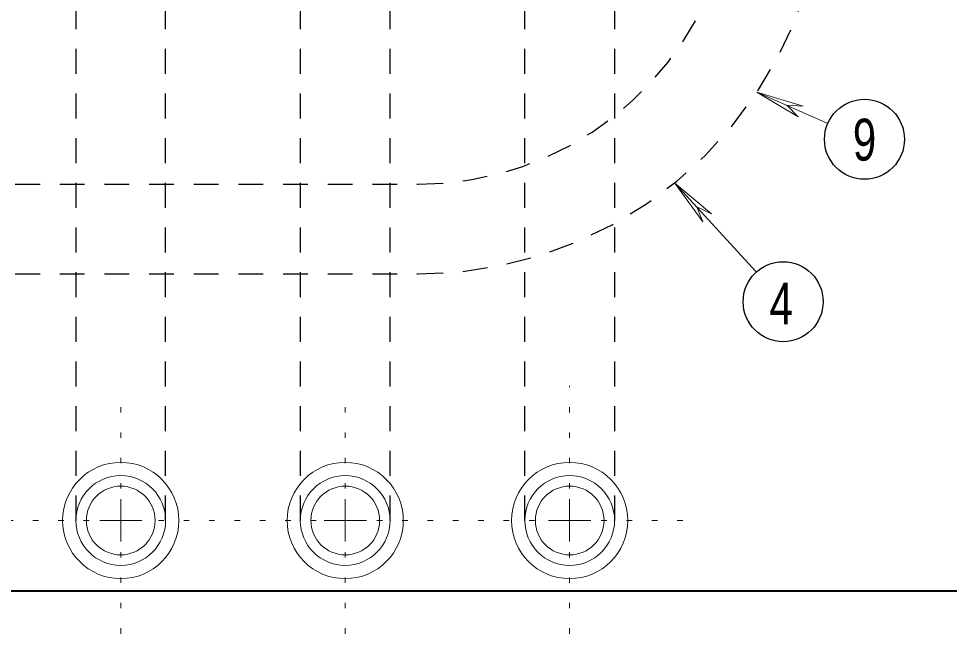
# Model space of a CAD drawing. Extents: x 312583 to 312854, y 144419 to 144597.
# Drawn here: x 312756.71 to 312773.6, y 144437.08 to 144448.42 of the extents above; entities that cross this region are included whole.
import ezdxf

# ---------------------------------------------------------------- set-up
doc = ezdxf.new("R2010")
doc.units = 0
doc.header["$LTSCALE"] = 0.3
doc.linetypes.add('DOTTED', pattern=[1.5, 0.3, -1.2])
doc.linetypes.add('SHORT_DASHED', pattern=[2.7, 1.5, -1.2])
doc.layers.add('1', color=7, linetype='Continuous', lineweight=25)
doc.layers.add('2', color=7, linetype='Continuous', lineweight=13)

msp = doc.modelspace()

# ---------------------------------------------------------------- linework, layer by layer
at = {"layer": '1', "linetype": 'SHORT_DASHED'}
for p, q in [((312757.7576, 144439.315), (312757.7576, 144450.654)), ((312759.383, 144439.315), (312759.383, 144449.182)), ((312761.8286, 144439.315), (312761.8286, 144449.1974)), ((312763.454, 144439.315), (312763.454, 144449.113)), ((312767.5326, 144439.315), (312767.5326, 144448.9827)), ((312765.8996, 144439.315), (312765.8996, 144448.9444)), ((312754.2233, 144445.41), (312763.9676, 144445.41)), ((312754.2233, 144443.7847), (312763.9676, 144443.7847))]:
    msp.add_line(p, q, dxfattribs=at)
at = {"layer": '1', "lineweight": 40}
msp.add_line((312733.8913, 144438.0347), (312778.611, 144438.0347), dxfattribs=at)
at = {"layer": '1', "lineweight": 13}
for centre, radius in [((312758.5684, 144439.3125), 1.0542), ((312762.6413, 144439.3125), 1.0542), ((312766.7142, 144439.3125), 1.0542), ((312758.5684, 144439.3125), 0.8146), ((312762.6413, 144439.3125), 0.8146), ((312766.7142, 144439.3125), 0.8146), ((312758.5684, 144439.3125), 0.6232), ((312762.6413, 144439.3125), 0.6232), ((312766.7142, 144439.3125), 0.6232)]:
    msp.add_circle(centre, radius, dxfattribs=at)
at = {"layer": '1', "linetype": 'SHORT_DASHED'}
for radius, end in [(7.3792, 0), (5.75, 345.9494)]:
    msp.add_arc((312763.967, 144451.1639), radius, 270, end, dxfattribs=at)
at = {"layer": '2'}
for p, q in [((312771.3966, 144446.514), (312770.1086, 144447.0814)), ((312770.1086, 144447.0814), (312770.86, 144446.6367)), ((312770.1086, 144447.0814), (312770.952, 144446.8284)), ((312770.86, 144446.6367), (312770.653, 144446.8437)), ((312770.952, 144446.8284), (312770.653, 144446.8437)), ((312770.101, 144443.823), (312768.6213, 144445.433)), ((312768.6213, 144445.433), (312769.1273, 144444.7277)), ((312768.6213, 144445.433), (312769.2883, 144444.8734)), ((312769.1273, 144444.7277), (312769.02, 144445.0037)), ((312769.2883, 144444.8734), (312769.02, 144445.0037)), ((312758.5703, 144439.315), (312758.5703, 144439.6984)), ((312762.6413, 144439.315), (312762.6413, 144439.6984)), ((312766.7123, 144439.315), (312766.7123, 144439.6984)), ((312758.5703, 144439.315), (312758.187, 144439.315)), ((312758.5703, 144439.315), (312758.9536, 144439.315)), ((312758.5703, 144439.315), (312758.5703, 144438.9317)), ((312762.6413, 144439.315), (312762.258, 144439.315)), ((312762.6413, 144439.315), (312763.0246, 144439.315)), ((312762.6413, 144439.315), (312762.6413, 144438.9317)), ((312766.7123, 144439.315), (312766.329, 144439.315)), ((312766.7123, 144439.315), (312767.0956, 144439.315)), ((312766.7123, 144439.315), (312766.7123, 144438.9317))]:
    msp.add_line(p, q, dxfattribs=at)
at = {"layer": '2', "linetype": 'DOTTED'}
for p, q in [((312766.7123, 144439.89), (312766.7123, 144441.753)), ((312758.5703, 144439.89), (312758.5703, 144441.6457)), ((312762.6413, 144439.89), (312762.6413, 144441.6917)), ((312757.9953, 144439.315), (312756.1783, 144439.315)), ((312762.1123, 144439.315), (312759.0916, 144439.315)), ((312763.2163, 144439.315), (312766.1756, 144439.315)), ((312767.2873, 144439.315), (312768.9433, 144439.315)), ((312758.5703, 144438.74), (312758.5703, 144437.1224)), ((312762.6413, 144438.74), (312762.6413, 144437.084)), ((312766.7123, 144438.74), (312766.7123, 144437.1607))]:
    msp.add_line(p, q, dxfattribs=at)
at = {"layer": '2', "lineweight": 25}
for centre in [(312772.0636, 144446.2265), (312770.5878, 144443.2814)]:
    msp.add_circle(centre, 0.7254, dxfattribs=at)

# ---------------------------------------------------------------- texts
at = {"layer": '2', "width": 0.75}
for s, p in [('9', (312771.8519, 144445.8402)), ('4', (312770.3404, 144442.8679))]:
    msp.add_text(s, height=0.76, dxfattribs=at).set_placement(p)

doc.saveas('drawing.dxf')
